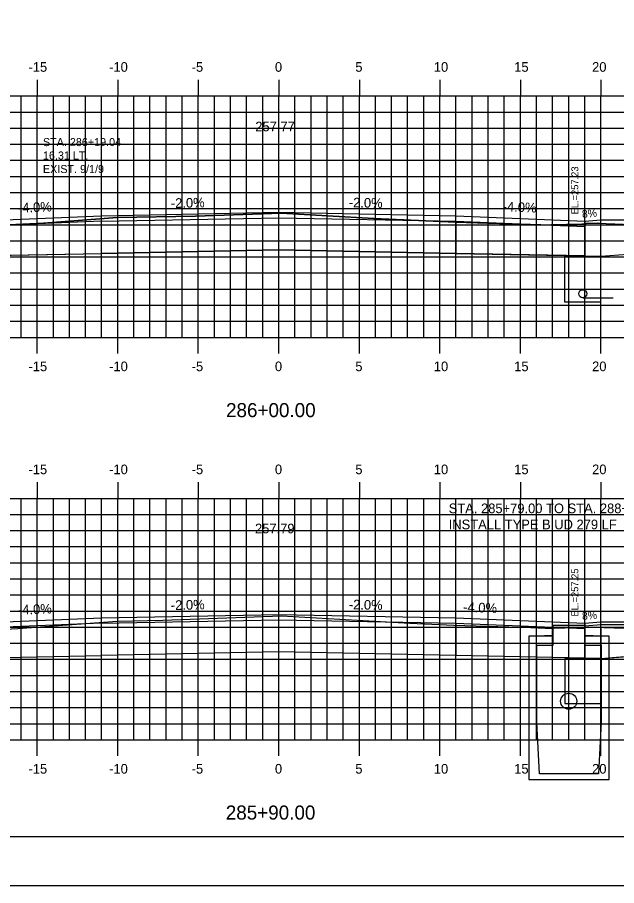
# Model space of a CAD drawing. Extents: x 856903 to 857073, y 366268 to 366378.
# Drawn here: x 856969.5 to 857006.8, y 366268.2 to 366322.1 of the extents above; entities that cross this region are included whole.
import ezdxf

# ---------------------------------------------------------------- set-up
doc = ezdxf.new("R2010")
doc.units = 0
for name, color, linetype in [('ANNOTATION', 7, 'Continuous'), ('BORDER', 7, 'Continuous'), ('D_Drainage_CB_TypeA1-B1', 7, 'Continuous'), ('D_Drainage_Text', 7, 'Continuous'), ('D_Roadway_Centerline', 7, 'Continuous'), ('D_Roadway_Centerline_Text', 7, 'Continuous'), ('D_Roadway_Drive_Gravel_LT', 7, 'Continuous'), ('D_Roadway_Drive_Gravel_RT', 7, 'Continuous'), ('D_Roadway_Drive_SubGrade', 7, 'Continuous'), ('D_Roadway_Edge_Shoulder', 7, 'Continuous'), ('D_Roadway_SubGrade', 7, 'Continuous'), ('D_Text_Monospaced', 7, 'Continuous'), ('D_Text_Standard', 7, 'Continuous'), ('H_V ANNOTATION', 7, 'Continuous'), ('JUNK COM EXC', 7, 'Continuous'), ('junk strct exc', 7, 'Continuous'), ('MAJOR', 7, 'Continuous'), ('MINOR', 7, 'Continuous'), ('PDRAIN', 7, 'Continuous'), ('PLOT BOUNDARY', 7, 'Continuous'), ('S_Roadway_Centerline', 7, 'Continuous')]:
    doc.layers.add(name, color=color, linetype=linetype)

msp = doc.modelspace()

# ---------------------------------------------------------------- linework, layer by layer
at = {"layer": 'BORDER'}
msp.add_line((856910.784, 366271.236), (857070.784, 366271.236), dxfattribs=at)
at = {"layer": 'D_Drainage_CB_TypeA1-B1'}
for p, q in [((857001.798, 366283.685), (857001.306, 366283.685)), ((857001.306, 366283.685), (857001.306, 366274.771)), ((857002.815, 366283.685), (857001.798, 366283.685)), ((857005.801, 366283.685), (857004.784, 366283.685)), ((857006.293, 366283.685), (857005.801, 366283.685)), ((857006.293, 366274.771), (857006.293, 366283.685)), ((857001.798, 366278.337), (857001.798, 366281.683)), ((857005.801, 366281.683), (857005.801, 366278.337)), ((857001.962, 366275.132), (857001.798, 366278.337)), ((857005.801, 366278.337), (857005.637, 366275.132)), ((857005.637, 366275.132), (857001.962, 366275.132)), ((857001.306, 366274.771), (857006.293, 366274.771))]:
    msp.add_line(p, q, dxfattribs=at)
for points in [[(857002.291, 366283.726), (857002.815, 366283.726), (857002.815, 366284.35), (857004.784, 366284.35), (857004.784, 366283.726), (857005.309, 366283.726)], [(857001.798, 366281.683), (857001.798, 366283.107), (857002.815, 366283.107), (857002.815, 366283.685)], [(857004.784, 366283.685), (857004.784, 366283.107), (857005.801, 366283.107), (857005.801, 366281.683)]]:
    msp.add_lwpolyline(points, dxfattribs=at)
at = {"layer": 'D_Roadway_Centerline'}
for points in [[(856974.784, 366309.786), (856985.784, 366310.006), (856996.784, 366309.786)], [(856996.784, 366309.785), (857004.781, 366309.466), (857004.784, 366309.465)], [(856974.784, 366284.811), (856985.784, 366285.031), (856996.784, 366284.811)]]:
    msp.add_lwpolyline(points, dxfattribs=at)
at = {"layer": 'D_Roadway_Drive_Gravel_LT'}
for p, q in [((857005.781, 366309.546), (857009.781, 366309.546)), ((857005.785, 366284.571), (857009.785, 366284.571)), ((857005.785, 366284.404), (857009.785, 366284.404))]:
    msp.add_line(p, q, dxfattribs=at)
at = {"layer": 'D_Roadway_Drive_Gravel_RT'}
for p, q in [((857004.781, 366309.466), (857005.781, 366309.546)), ((857004.784, 366284.324), (857005.798, 366284.405)), ((857004.785, 366284.491), (857005.785, 366284.571))]:
    msp.add_line(p, q, dxfattribs=at)
at = {"layer": 'D_Roadway_Drive_SubGrade'}
for p, q in [((857005.781, 366307.272), (857015.784, 366308.025)), ((857004.781, 366307.292), (857005.781, 366307.272)), ((857005.784, 366282.297), (857015.784, 366283.042)), ((857004.784, 366282.317), (857005.784, 366282.297))]:
    msp.add_line(p, q, dxfattribs=at)
at = {"layer": 'D_Roadway_Edge_Shoulder'}
for p, q in [((857004.785, 366309.466), (857004.784, 366309.132)), ((857004.785, 366284.491), (857004.784, 366284.157))]:
    msp.add_line(p, q, dxfattribs=at)
for points in [[(856966.784, 366309.466), (856974.784, 366309.786), (856985.784, 366310.006), (856996.784, 366309.786), (857004.785, 366309.466)], [(856966.784, 366284.491), (856974.784, 366284.811), (856985.784, 366285.031), (856996.784, 366284.811), (857004.785, 366284.491)]]:
    msp.add_lwpolyline(points, dxfattribs=at)
at = {"layer": 'D_Roadway_SubGrade'}
for points in [[(856974.784, 366307.452), (856974.784, 366309.452), (856985.784, 366309.672), (856996.784, 366309.452), (856996.784, 366307.452), (856985.784, 366307.672)], [(856974.784, 366309.452), (856966.784, 366309.132), (856966.784, 366307.292), (856974.784, 366307.452)], [(856996.784, 366309.452), (857004.784, 366309.132), (857004.784, 366307.292), (856996.784, 366307.452)], [(856974.784, 366282.477), (856974.784, 366284.477), (856985.784, 366284.697), (856996.784, 366284.477), (856996.784, 366282.477), (856985.784, 366282.697)], [(856974.784, 366284.477), (856966.784, 366284.157), (856966.784, 366282.317), (856974.784, 366282.477)], [(856996.784, 366284.477), (857004.784, 366284.157), (857004.784, 366282.317), (856996.784, 366282.477)]]:
    msp.add_lwpolyline(points, close=True, dxfattribs=at)
at = {"layer": 'D_Text_Standard'}
msp.add_lwpolyline([(857004.656, 366304.696), (857005.871, 366304.696), (857006.551, 366304.696)], dxfattribs=at)
at = {"layer": 'JUNK COM EXC'}
for points in [[(856965.784, 366307.272), (856974.784, 366307.452), (856985.784, 366307.672), (856996.784, 366307.452), (857005.781, 366307.272), (857005.781, 366309.318), (857005.591, 366309.325), (857004.879, 366309.319), (857004.597, 366309.268), (857002.698, 366309.225), (857002.68, 366309.2), (857000.171, 366309.291), (856996.749, 366309.39), (856991.679, 366309.628), (856985.933, 366309.959), (856980.618, 366309.765), (856975.751, 366309.678), (856971.171, 366309.335), (856967.725, 366309.157)], [(857005.784, 366284.218), (857005.784, 366282.297), (857005.784, 366282.297), (857015.079, 366283.084), (857026.517, 366282.398), (857026.517, 366283.567), (857022.035, 366283.697), (857005.784, 366284.218)]]:
    msp.add_lwpolyline(points, dxfattribs=at)
at = {"layer": 'junk strct exc'}
for points in [[(857003.531, 366307.247), (857003.531, 366304.446), (857005.781, 366304.446), (857005.781, 366307.247)], [(857003.534, 366282.297), (857003.534, 366279.496), (857005.784, 366279.496), (857005.784, 366282.297)]]:
    msp.add_lwpolyline(points, close=True, dxfattribs=at)
at = {"layer": 'MAJOR'}
for p, q in [((856970.784, 366318.238), (856970.784, 366317.236)), ((856975.784, 366318.238), (856975.784, 366317.236)), ((856980.784, 366318.238), (856980.784, 366317.236)), ((856985.784, 366318.238), (856985.784, 366317.236)), ((856990.784, 366318.238), (856990.784, 366317.236)), ((856995.784, 366318.238), (856995.784, 366317.236)), ((857000.784, 366318.238), (857000.784, 366317.236)), ((857005.784, 366318.238), (857005.784, 366317.236)), ((856915.784, 366317.236), (857055.784, 366317.236)), ((856915.784, 366317.236), (857055.784, 366317.236)), ((856970.784, 366302.236), (856970.784, 366317.236)), ((856975.784, 366302.236), (856975.784, 366317.236)), ((856980.784, 366302.236), (856980.784, 366317.236)), ((856985.784, 366302.236), (856985.784, 366317.236)), ((856990.784, 366302.236), (856990.784, 366317.236)), ((856995.784, 366302.236), (856995.784, 366317.236)), ((857000.784, 366302.236), (857000.784, 366317.236)), ((857005.784, 366302.236), (857005.784, 366317.236)), ((856915.784, 366312.236), (857055.784, 366312.236)), ((856915.784, 366307.236), (857055.784, 366307.236)), ((856915.784, 366302.236), (857055.784, 366302.236)), ((856915.784, 366302.236), (857055.784, 366302.236)), ((856970.784, 366301.234), (856970.784, 366302.236)), ((856975.784, 366301.234), (856975.784, 366302.236)), ((856980.784, 366301.234), (856980.784, 366302.236)), ((856985.784, 366301.234), (856985.784, 366302.236)), ((856990.784, 366301.234), (856990.784, 366302.236)), ((856995.784, 366301.234), (856995.784, 366302.236)), ((857000.784, 366301.234), (857000.784, 366302.236)), ((857005.784, 366301.234), (857005.784, 366302.236)), ((856970.784, 366293.238), (856970.784, 366292.236)), ((856975.784, 366293.238), (856975.784, 366292.236)), ((856980.784, 366293.238), (856980.784, 366292.236)), ((856985.784, 366293.238), (856985.784, 366292.236)), ((856990.784, 366293.238), (856990.784, 366292.236)), ((856995.784, 366293.238), (856995.784, 366292.236)), ((857000.784, 366293.238), (857000.784, 366292.236)), ((857005.784, 366293.238), (857005.784, 366292.236)), ((856915.784, 366292.236), (857055.784, 366292.236)), ((856915.784, 366292.236), (857055.784, 366292.236)), ((856970.784, 366277.236), (856970.784, 366292.236)), ((856975.784, 366277.236), (856975.784, 366292.236)), ((856980.784, 366277.236), (856980.784, 366292.236)), ((856985.784, 366277.236), (856985.784, 366292.236)), ((856990.784, 366277.236), (856990.784, 366292.236)), ((856995.784, 366277.236), (856995.784, 366292.236)), ((857000.784, 366277.236), (857000.784, 366292.236)), ((857005.784, 366277.236), (857005.784, 366292.236)), ((856915.784, 366287.236), (857055.784, 366287.236)), ((856915.784, 366282.236), (857055.784, 366282.236)), ((856915.784, 366277.236), (857055.784, 366277.236)), ((856915.784, 366277.236), (857055.784, 366277.236)), ((856970.784, 366276.234), (856970.784, 366277.236)), ((856975.784, 366276.234), (856975.784, 366277.236)), ((856980.784, 366276.234), (856980.784, 366277.236)), ((856985.784, 366276.234), (856985.784, 366277.236)), ((856990.784, 366276.234), (856990.784, 366277.236)), ((856995.784, 366276.234), (856995.784, 366277.236)), ((857000.784, 366276.234), (857000.784, 366277.236)), ((857005.784, 366276.234), (857005.784, 366277.236))]:
    msp.add_line(p, q, dxfattribs=at)
at = {"layer": 'MINOR'}
for p, q in [((856969.784, 366302.236), (856969.784, 366317.236)), ((856971.784, 366302.236), (856971.784, 366317.236)), ((856972.784, 366302.236), (856972.784, 366317.236)), ((856973.784, 366302.236), (856973.784, 366317.236)), ((856974.784, 366302.236), (856974.784, 366317.236)), ((856976.784, 366302.236), (856976.784, 366317.236)), ((856977.784, 366302.236), (856977.784, 366317.236)), ((856978.784, 366302.236), (856978.784, 366317.236)), ((856979.784, 366302.236), (856979.784, 366317.236)), ((856981.784, 366302.236), (856981.784, 366317.236)), ((856982.784, 366302.236), (856982.784, 366317.236)), ((856983.784, 366302.236), (856983.784, 366317.236)), ((856984.784, 366302.236), (856984.784, 366317.236)), ((856986.784, 366302.236), (856986.784, 366317.236)), ((856987.784, 366302.236), (856987.784, 366317.236)), ((856988.784, 366302.236), (856988.784, 366317.236)), ((856989.784, 366302.236), (856989.784, 366317.236)), ((856991.784, 366302.236), (856991.784, 366317.236)), ((856992.784, 366302.236), (856992.784, 366317.236)), ((856993.784, 366302.236), (856993.784, 366317.236)), ((856994.784, 366302.236), (856994.784, 366317.236)), ((856996.784, 366302.236), (856996.784, 366317.236)), ((856997.784, 366302.236), (856997.784, 366317.236)), ((856998.784, 366302.236), (856998.784, 366317.236)), ((856999.784, 366302.236), (856999.784, 366317.236)), ((857001.784, 366302.236), (857001.784, 366317.236)), ((857002.784, 366302.236), (857002.784, 366317.236)), ((857003.784, 366302.236), (857003.784, 366317.236)), ((857004.784, 366302.236), (857004.784, 366317.236)), ((856915.784, 366316.236), (857055.784, 366316.236)), ((856915.784, 366315.236), (857055.784, 366315.236)), ((856915.784, 366314.236), (857055.784, 366314.236)), ((856915.784, 366313.236), (857055.784, 366313.236)), ((856915.784, 366311.236), (857055.784, 366311.236)), ((856915.784, 366310.236), (857055.784, 366310.236)), ((856915.784, 366309.236), (857055.784, 366309.236)), ((856915.784, 366308.236), (857055.784, 366308.236)), ((856915.784, 366306.236), (857055.784, 366306.236)), ((856915.784, 366305.236), (857055.784, 366305.236)), ((856915.784, 366304.236), (857055.784, 366304.236)), ((856915.784, 366303.236), (857055.784, 366303.236)), ((856969.784, 366277.236), (856969.784, 366292.236)), ((856971.784, 366277.236), (856971.784, 366292.236)), ((856972.784, 366277.236), (856972.784, 366292.236)), ((856973.784, 366277.236), (856973.784, 366292.236)), ((856974.784, 366277.236), (856974.784, 366292.236)), ((856976.784, 366277.236), (856976.784, 366292.236)), ((856977.784, 366277.236), (856977.784, 366292.236)), ((856978.784, 366277.236), (856978.784, 366292.236)), ((856979.784, 366277.236), (856979.784, 366292.236)), ((856981.784, 366277.236), (856981.784, 366292.236)), ((856982.784, 366277.236), (856982.784, 366292.236)), ((856983.784, 366277.236), (856983.784, 366292.236)), ((856984.784, 366277.236), (856984.784, 366292.236)), ((856986.784, 366277.236), (856986.784, 366292.236)), ((856987.784, 366277.236), (856987.784, 366292.236)), ((856988.784, 366277.236), (856988.784, 366292.236)), ((856989.784, 366277.236), (856989.784, 366292.236)), ((856991.784, 366277.236), (856991.784, 366292.236)), ((856992.784, 366277.236), (856992.784, 366292.236)), ((856993.784, 366277.236), (856993.784, 366292.236)), ((856994.784, 366277.236), (856994.784, 366292.236)), ((856996.784, 366277.236), (856996.784, 366292.236)), ((856997.784, 366277.236), (856997.784, 366292.236)), ((856998.784, 366277.236), (856998.784, 366292.236)), ((856999.784, 366277.236), (856999.784, 366292.236)), ((857001.784, 366277.236), (857001.784, 366292.236)), ((857002.784, 366277.236), (857002.784, 366292.236)), ((857003.784, 366277.236), (857003.784, 366292.236)), ((857004.784, 366277.236), (857004.784, 366292.236)), ((856915.784, 366291.236), (857055.784, 366291.236)), ((856915.784, 366290.236), (857055.784, 366290.236)), ((856915.784, 366289.236), (857055.784, 366289.236)), ((856915.784, 366288.236), (857055.784, 366288.236)), ((856915.784, 366286.236), (857055.784, 366286.236)), ((856915.784, 366285.236), (857055.784, 366285.236)), ((856915.784, 366284.236), (857055.784, 366284.236)), ((856915.784, 366283.236), (857055.784, 366283.236)), ((856915.784, 366281.236), (857055.784, 366281.236)), ((856915.784, 366280.236), (857055.784, 366280.236)), ((856915.784, 366279.236), (857055.784, 366279.236)), ((856915.784, 366278.236), (857055.784, 366278.236))]:
    msp.add_line(p, q, dxfattribs=at)
at = {"layer": 'PDRAIN'}
msp.add_lwpolyline([(857003.531, 366307.318), (857003.531, 366304.446), (857005.781, 366304.446), (857005.781, 366307.272)], dxfattribs=at)
for centre, radius in [((857004.656, 366304.946), 0.25), ((857003.784, 366279.632), 0.5)]:
    msp.add_circle(centre, radius, dxfattribs=at)
at = {"layer": 'PLOT BOUNDARY'}
msp.add_lwpolyline([(856902.691, 366268.177), (857072.691, 366268.177), (857072.691, 366378.177), (856902.691, 366378.177)], close=True, dxfattribs=at)
at = {"layer": 'S_Roadway_Centerline'}
for points in [[(856967.725, 366309.157), (856971.171, 366309.335), (856975.751, 366309.678), (856980.618, 366309.765), (856985.933, 366309.959), (856991.679, 366309.628), (856996.749, 366309.39), (857000.171, 366309.291), (857002.68, 366309.2), (857002.698, 366309.225), (857004.597, 366309.268), (857004.879, 366309.319), (857005.591, 366309.325), (857011.392, 366309.107), (857019.528, 366308.881), (857037.887, 366308.346)], [(856928.638, 366284.466), (856941.425, 366284.86), (856945.596, 366284.966), (856952.237, 366285.026), (856963.162, 366284.875), (856963.518, 366284.787), (856963.712, 366284.697), (856965.326, 366284.666), (856967.014, 366284.586), (856967.196, 366284.361), (856967.593, 366284.051), (856969.584, 366284.154), (856975.753, 366284.616), (856978.579, 366284.666), (856985.947, 366284.936), (856993.912, 366284.477), (856996.656, 366284.348), (857001.427, 366284.21), (857002.776, 366284.161), (857002.786, 366284.174), (857004.302, 366284.209), (857005.32, 366284.233), (857022.035, 366283.697), (857037.595, 366283.244)]]:
    msp.add_lwpolyline(points, dxfattribs=at)

# ---------------------------------------------------------------- texts
at = {"layer": 'ANNOTATION'}
for s, rotation, p in [('-4.0%', 2.2906, (856969.6, 366309.979)), ('-2.0%', 1.1458, (856979.087, 366310.272)), ('-2.0%', 358.8542, (856990.127, 366310.319)), ('-4.0%', 357.7094, (856999.678, 366310.071)), ('-2.0%', 1.1458, (856979.087, 366285.297)), ('-2.0%', 358.8542, (856990.127, 366285.344)), ('-4.0%', 357.7095, (856997.225, 366285.194)), ('-4.0%', 2.2906, (856969.6, 366285.004))]:
    msp.add_text(s, height=0.6, rotation=rotation, dxfattribs=at).set_placement(p)
at = {"layer": 'D_Drainage_Text'}
for s, p in [('STA. 285+79.00 TO STA. 288+58.00 RT', (856996.334, 366291.315)), ('INSTALL TYPE B UD 279 LF', (856996.334, 366290.315))]:
    msp.add_text(s, height=0.6, dxfattribs=at).set_placement(p)
at = {"layer": 'D_Roadway_Centerline_Text'}
for s, p in [('257.77', (856984.323, 366315.038)), ('257.79', (856984.307, 366290.063))]:
    msp.add_text(s, height=0.6, dxfattribs=at).set_placement(p)
at = {"layer": 'D_Roadway_Drive_Gravel_RT'}
for p in [(857004.628, 366309.659), (857004.632, 366284.684)]:
    msp.add_text('8%', height=0.48, rotation=4.5739, dxfattribs=at).set_placement(p)
at = {"layer": 'D_Text_Monospaced'}
for s, height, p in [('STA. 286+19.04', 0.49998, (856971.138, 366314.119)), ('16.31 LT.', 0.5, (856971.138, 366313.285)), ('EXIST. 9/1/9', 0.49998, (856971.138, 366312.445))]:
    msp.add_text(s, height=height, dxfattribs=at).set_placement(p)
at = {"layer": 'D_Text_Standard'}
for s, p in [(' EL.=257.23', (857004.382, 366309.711)), (' EL.=257.25', (857004.382, 366284.736))]:
    msp.add_text(s, height=0.4335, rotation=90, dxfattribs=at).set_placement(p)
at = {"layer": 'H_V ANNOTATION'}
for s, height, p in [('-15', 0.6, (856970.241, 366318.736)), ('-10', 0.6, (856975.249, 366318.736)), ('-5', 0.6, (856980.375, 366318.736)), ('0', 0.6, (856985.543, 366318.736)), ('5', 0.6, (856990.535, 366318.736)), ('10', 0.6, (856995.409, 366318.736)), ('15', 0.6, (857000.401, 366318.736)), ('20', 0.6, (857005.238, 366318.736)), ('-15', 0.6, (856970.241, 366300.136)), ('-10', 0.6, (856975.249, 366300.136)), ('-5', 0.6, (856980.375, 366300.136)), ('0', 0.6, (856985.543, 366300.136)), ('5', 0.6, (856990.535, 366300.136)), ('10', 0.6, (856995.409, 366300.136)), ('15', 0.6, (857000.401, 366300.136)), ('20', 0.6, (857005.238, 366300.136)), ('286+00.00', 0.875, (856982.507, 366297.28)), ('-15', 0.6, (856970.241, 366293.736)), ('-10', 0.6, (856975.249, 366293.736)), ('-5', 0.6, (856980.375, 366293.736)), ('0', 0.6, (856985.543, 366293.736)), ('5', 0.6, (856990.535, 366293.736)), ('10', 0.6, (856995.409, 366293.736)), ('15', 0.6, (857000.401, 366293.736)), ('20', 0.6, (857005.238, 366293.736)), ('-15', 0.6, (856970.241, 366275.136)), ('-10', 0.6, (856975.249, 366275.136)), ('-5', 0.6, (856980.375, 366275.136)), ('0', 0.6, (856985.543, 366275.136)), ('5', 0.6, (856990.535, 366275.136)), ('10', 0.6, (856995.409, 366275.136)), ('15', 0.6, (857000.401, 366275.136)), ('20', 0.6, (857005.238, 366275.136)), ('285+90.00', 0.875, (856982.491, 366272.28))]:
    msp.add_text(s, height=height, dxfattribs=at).set_placement(p)
at = {"layer": 'S_Roadway_Centerline'}
for s, p in [('C', (856985.928, 366309.959)), ('L', (856985.933, 366309.952)), ('C', (856985.942, 366284.936)), ('L', (856985.947, 366284.929))]:
    msp.add_text(s, height=0.0146, dxfattribs=at).set_placement(p)

doc.saveas('drawing.dxf')
